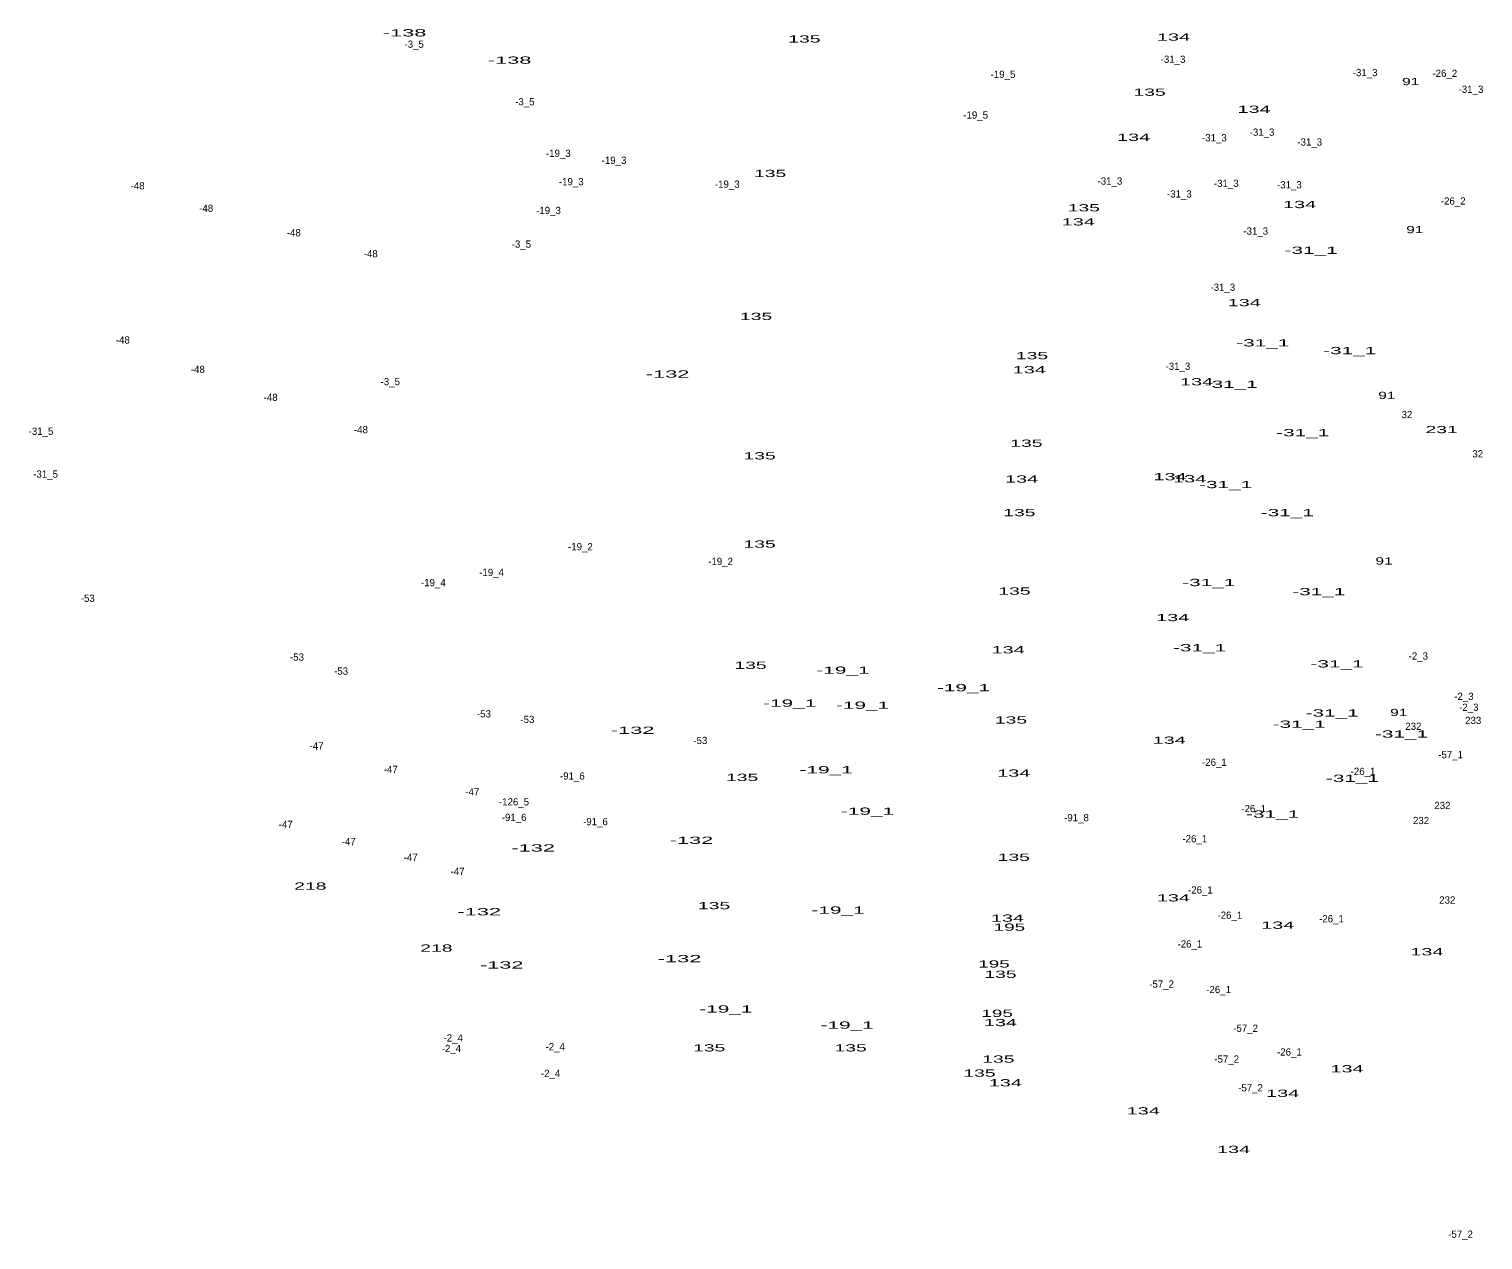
# Model space of a CAD drawing. Extents: x -656096 to -652763, y -1002270 to -998958.
# Drawn here: x -655716 to -654912, y -1002062 to -1001392 of the extents above; entities that cross this region are included whole.
import ezdxf
from ezdxf.enums import TextEntityAlignment as Align

# ---------------------------------------------------------------- set-up
doc = ezdxf.new("R2010")
doc.units = 0
doc.header["$LTSCALE"] = 1.6
doc.layers.add('24', color=7, linetype='Continuous')

msp = doc.modelspace()

# ---------------------------------------------------------------- texts
at = {"layer": '24'}
for s, width, p in [('-138', 2.25, (-655508.081, -1001396.4)), ('134', 2.05, (-655082.813, -1001398.74)), ('135', 2, (-655286.957, -1001399.78)), ('-138', 2.25, (-655449.991, -1001411.51)), ('135', 2, (-655096.037, -1001429.22)), ('91', 1.6, (-654951.663, -1001423.33)), ('134', 2.05, (-655038.273, -1001438.65)), ('134', 2.05, (-655104.883, -1001454.14)), ('135', 2, (-655305.927, -1001474.16)), ('135', 2, (-655132.437, -1001493.14)), ('134', 2.05, (-655013.103, -1001491.33)), ('134', 2.05, (-655135.483, -1001500.92)), ('91', 1.6, (-654949.333, -1001505.17)), ('-31_1', 2.15, (-655006.707, -1001516.62)), ('134', 2.05, (-655043.693, -1001545.57)), ('135', 2, (-655313.677, -1001553.19)), ('135', 2, (-655161.097, -1001574.89)), ('-31_1', 2.15, (-655033.457, -1001567.82)), ('-31_1', 2.15, (-654985.377, -1001572.09)), ('134', 2.05, (-655162.583, -1001582.67)), ('-132', 2.25, (-655362.611, -1001585.07)), ('134', 2.05, (-655070.033, -1001589.35)), ('-31_1', 2.15, (-655050.907, -1001590.71)), ('91', 1.6, (-654964.843, -1001596.87)), ('231', 2, (-654934.547, -1001615.75)), ('135', 2, (-655164.187, -1001623.31)), ('-31_1', 2.15, (-655011.357, -1001617.47)), ('135', 2, (-655311.737, -1001630.29)), ('134', 2.05, (-655166.843, -1001643.1)), ('134', 2.05, (-655084.743, -1001641.82)), ('134', 2.05, (-655073.903, -1001642.98)), ('-31_1', 2.15, (-655054.007, -1001646.17)), ('135', 2, (-655168.067, -1001661.67)), ('-31_1', 2.15, (-655019.887, -1001661.69)), ('135', 2, (-655311.737, -1001679.09)), ('91', 1.6, (-654966.393, -1001688.41)), ('-31_1', 2.15, (-655063.317, -1001700.33)), ('135', 2, (-655170.777, -1001705.05)), ('-31_1', 2.15, (-655002.437, -1001705.37)), ('134', 2.05, (-655083.273, -1001719.72)), ('-31_1', 2.15, (-655068.357, -1001736.4)), ('134', 2.05, (-655174.283, -1001737.54)), ('135', 2, (-655316.777, -1001746.11)), ('-19_1', 2.15, (-655265.653, -1001748.79)), ('-31_1', 2.15, (-654992.357, -1001745.32)), ('-19_1', 2.15, (-655198.963, -1001758.49)), ('-19_1', 2.15, (-655295.123, -1001767.02)), ('-19_1', 2.15, (-655254.803, -1001768.19)), ('135', 2, (-655172.707, -1001776.33)), ('-31_1', 2.15, (-654995.067, -1001772.47)), ('91', 1.6, (-654958.253, -1001772.19)), ('-132', 2.25, (-655381.971, -1001782.03)), ('-31_1', 2.15, (-655013.297, -1001778.68)), ('-31_1', 2.15, (-654956.687, -1001784.11)), ('134', 2.05, (-655085.213, -1001787.52)), ('135', 2, (-655321.417, -1001808.1)), ('-19_1', 2.15, (-655274.963, -1001803.87)), ('134', 2.05, (-655171.183, -1001805.73)), ('-31_1', 2.15, (-654983.827, -1001808.61)), ('-19_1', 2.15, (-655252.083, -1001826.76)), ('-31_1', 2.15, (-655028.027, -1001828.39)), ('-132', 2.25, (-655436.961, -1001847.11)), ('-132', 2.25, (-655349.441, -1001842.85)), ('135', 2, (-655171.157, -1001852.26)), ('218', 2, (-655560.207, -1001868.19)), ('135', 2, (-655336.917, -1001878.99)), ('134', 2.05, (-655082.883, -1001874.69)), ('-132', 2.25, (-655466.781, -1001882.37)), ('-19_1', 2.15, (-655268.373, -1001881.45)), ('134', 2.05, (-655174.673, -1001885.92)), ('195', 1.95, (-655173.593, -1001890.9)), ('134', 2.05, (-655025.183, -1001889.8)), ('218', 2, (-655490.497, -1001902.48)), ('134', 2.05, (-654942.693, -1001904.52)), ('-132', 2.25, (-655454.391, -1001911.81)), ('-132', 2.25, (-655356.021, -1001908.32)), ('195', 1.95, (-655182.113, -1001911.24)), ('135', 2, (-655178.517, -1001916.96)), ('-19_1', 2.15, (-655330.403, -1001936.14)), ('-19_1', 2.15, (-655263.333, -1001945.06)), ('195', 1.95, (-655180.373, -1001938.55)), ('134', 2.05, (-655178.543, -1001943.65)), ('135', 2, (-655339.627, -1001957.64)), ('135', 2, (-655261.397, -1001957.64)), ('135', 2, (-655179.677, -1001963.84)), ('134', 2.05, (-654986.843, -1001969.22)), ('135', 2, (-655190.137, -1001971.58)), ('134', 2.05, (-655175.833, -1001976.96)), ('134', 2.05, (-655022.473, -1001982.77)), ('134', 2.05, (-655099.543, -1001992.46)), ('134', 2.05, (-655049.583, -1002013.77))]:
    msp.add_text(s, height=4, dxfattribs=dict(at, width=width)).set_placement(p, align=Align.CENTER)
for s, p in [('-3_5', (-655502.813, -1001402.69)), ('-31_3', (-655083.086, -1001411)), ('-19_5', (-655177.112, -1001419.34)), ('-31_3', (-654976.846, -1001418.36)), ('-26_2', (-654932.768, -1001418.8)), ('-31_3', (-654918.296, -1001427.61)), ('-3_5', (-655441.553, -1001434.49)), ('-19_5', (-655192.232, -1001441.84)), ('-31_3', (-655060.206, -1001454.44)), ('-31_3', (-655033.846, -1001451.33)), ('-19_3', (-655423.072, -1001463.01)), ('-31_3', (-655007.476, -1001456.76)), ('-19_3', (-655392.252, -1001466.88)), ('-19_3', (-655415.902, -1001478.71)), ('-31_3', (-655117.986, -1001478.37)), ('-48', (-655655.759, -1001481)), ('-19_3', (-655329.632, -1001480.07)), ('-31_3', (-655079.596, -1001485.47)), ('-31_3', (-655053.616, -1001479.65)), ('-31_3', (-655018.726, -1001480.43)), ('-48', (-655617.809, -1001493.39)), ('-19_3', (-655428.502, -1001494.62)), ('-26_2', (-654928.118, -1001489.39)), ('-48', (-655569.399, -1001506.95)), ('-31_3', (-655037.336, -1001506.03)), ('-48', (-655526.799, -1001518.58)), ('-3_5', (-655443.493, -1001513.23)), ('-31_3', (-655055.556, -1001537.06)), ('-48', (-655663.899, -1001566.23)), ('-48', (-655622.459, -1001582.5)), ('-31_3', (-655080.376, -1001580.77)), ('-3_5', (-655515.993, -1001589.26)), ('-48', (-655582.179, -1001597.99)), ('32', (-654953.727, -1001607.47)), ('-48', (-655532.229, -1001615.82)), ('-31_5', (-655709.176, -1001616.71)), ('32', (-654914.567, -1001629.19)), ('-31_5', (-655706.656, -1001640.37)), ('-19_2', (-655410.852, -1001680.53)), ('-19_4', (-655459.996, -1001694.75)), ('-19_2', (-655333.312, -1001688.68)), ('-19_4', (-655492.176, -1001700.37)), ('-53', (-655683.315, -1001709.03)), ('-53', (-655567.605, -1001741.58)), ('-2_3', (-654947.423, -1001740.98)), ('-53', (-655543.205, -1001749.32)), ('-2_3', (-654922.213, -1001763.28)), ('-53', (-655464.205, -1001772.96)), ('-53', (-655440.195, -1001776.05)), ('-2_3', (-654919.503, -1001769.3)), ('233', (-654917.057, -1001776.56)), ('232', (-654950.167, -1001779.83)), ('-47', (-655556.795, -1001790.69)), ('-53', (-655344.535, -1001787.68)), ('-26_1', (-655060.202, -1001799.73)), ('-57_1', (-654929.572, -1001795.52)), ('-47', (-655515.745, -1001803.67)), ('-91_6', (-655415.317, -1001807.33)), ('-26_1', (-654978.002, -1001804.78)), ('-47', (-655470.625, -1001816.07)), ('-126_5', (-655447.582, -1001821.63)), ('232', (-654934.097, -1001823.61)), ('-91_6', (-655447.507, -1001830.22)), ('-91_6', (-655402.527, -1001832.54)), ('-91_8', (-655136.482, -1001830.34)), ('-26_1', (-655038.482, -1001825.33)), ('232', (-654945.907, -1001831.94)), ('-47', (-655573.835, -1001834.08)), ('-47', (-655538.965, -1001843.58)), ('-26_1', (-655071.052, -1001842.01)), ('-47', (-655504.705, -1001852.28)), ('-47', (-655478.755, -1001860.05)), ('-26_1', (-655067.952, -1001870.33)), ('232', (-654931.387, -1001875.91)), ('-26_1', (-655051.672, -1001884.29)), ('-26_1', (-654995.442, -1001886.23)), ('-26_1', (-655073.772, -1001900.19)), ('-57_2', (-655089.418, -1001922.39)), ('-26_1', (-655057.872, -1001925.41)), ('-2_4', (-655481.218, -1001952.16)), ('-57_2', (-655042.948, -1001946.8)), ('-2_4', (-655482.188, -1001957.98)), ('-2_4', (-655424.798, -1001957.01)), ('-26_1', (-655018.712, -1001959.93)), ('-57_2', (-655053.398, -1001963.84)), ('-2_4', (-655427.318, -1001971.75)), ('-57_2', (-655040.238, -1001979.73)), ('-57_2', (-654924.058, -1002060.69))]:
    msp.add_text(s, height=4, dxfattribs=at).set_placement(p, align=Align.CENTER)

doc.saveas('drawing.dxf')
